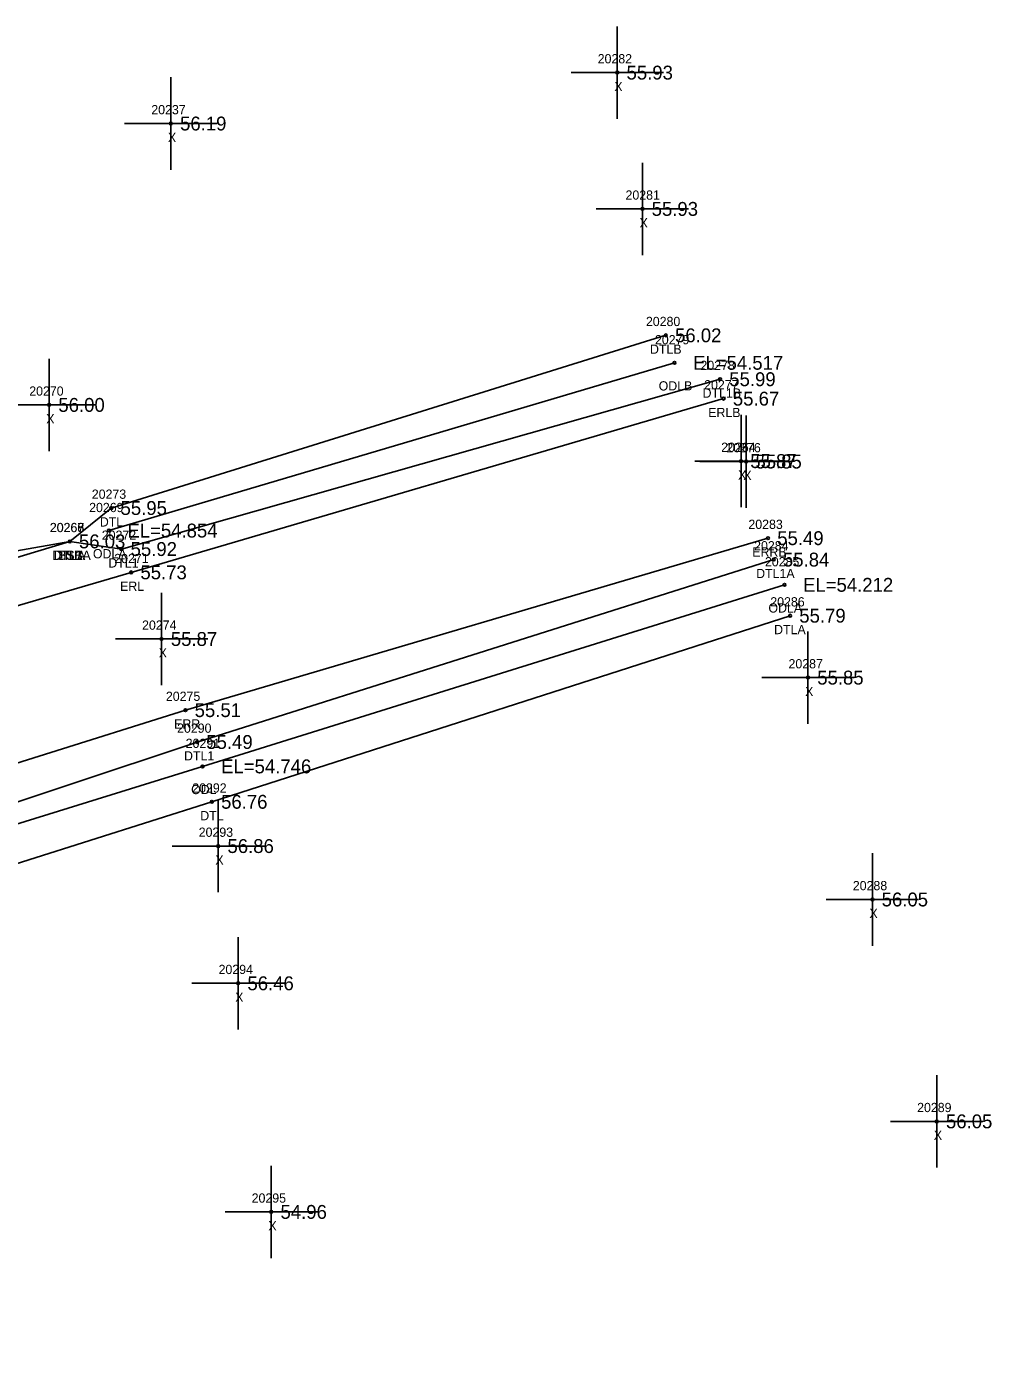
# Model space of a CAD drawing. Extents: x 2396547 to 2397655, y 770185 to 772649.
# Drawn here: x 2397051.2 to 2397155.6, y 771642.4 to 771785.4 of the extents above; entities that cross this region are included whole.
import ezdxf

# ---------------------------------------------------------------- set-up
doc = ezdxf.new("R2010")
doc.units = 0
for name, color, linetype in [('RD_DTM_BkLn2', 7, 'Continuous'), ('RD_DTM_BkLn_txCode', 7, 'Continuous'), ('RD_EX_H2O', 7, 'Continuous'), ('RD_EX_H2O_txCode', 7, 'Continuous'), ('RD_EX_Misc', 7, 'Continuous'), ('RD_EX_Misc_txCode', 7, 'Continuous'), ('RD_EX_Road', 7, 'Continuous'), ('RD_EX_Road_txCode', 7, 'Continuous'), ('RD_EX_TX_H2O_ELEV', 7, 'Continuous'), ('RD_EX_TX_Misc_ELEV', 7, 'Continuous'), ('RD_EX_TX_Road_ELEV', 7, 'Continuous'), ('RD_SMD_Locator', 7, 'Continuous')]:
    doc.layers.add(name, color=color, linetype=linetype)

msp = doc.modelspace()

# ---------------------------------------------------------------- linework, layer by layer
at = {"layer": 'RD_DTM_BkLn2'}
for points in [[(2397001.88, 771713.39), (2397031.24, 771722.25), (2397055.87, 771729.7)], [(2397001.88, 771713.39), (2397006.36, 771717.3), (2397030.46, 771725.22), (2397055.87, 771729.7)]]:
    msp.add_lwpolyline(points, dxfattribs=at)
at = {"layer": 'RD_EX_H2O'}
msp.add_line((2397060.11, 771730.87), (2397121.33, 771749.03), dxfattribs=at)
for points in [[(2397055.87, 771729.7), (2397060.37, 771733.31), (2397120.38, 771752)], [(2397055.87, 771729.7), (2397061.46, 771728.87), (2397126.25, 771747.25)], [(2397132.06, 771727.73), (2397069.65, 771707.99), (2397027.41, 771693.94), (2396997.29, 771683.71), (2397009.52, 771621.94), (2397039.8, 771510.33), (2397059.22, 771428.3), (2397068.26, 771415.82), (2397065.8, 771409.74)], [(2397133.23, 771725), (2397070.25, 771705.35), (2397027.65, 771692.13), (2397008.03, 771684.24), (2397003.46, 771682.97), (2397004.86, 771679.14), (2397019.55, 771624.25), (2397050.23, 771512.98), (2397072.95, 771431.23), (2397072.81, 771420.44), (2397072.44, 771413.81)], [(2397133.83, 771721.66), (2397071.25, 771701.52), (2397031.62, 771688.97), (2397008.91, 771681.79), (2397013.82, 771672.05), (2397025.11, 771625.88), (2397054.64, 771514.68), (2397075.97, 771429.94), (2397072.44, 771413.81)]]:
    msp.add_lwpolyline(points, dxfattribs=at)
at = {"layer": 'RD_EX_Misc'}
for p, q in [((2397115.13, 771775.43), (2397115.13, 771785.43)), ((2397066.81, 771769.92), (2397066.81, 771779.92)), ((2397110.13, 771780.43), (2397120.13, 771780.43)), ((2397061.81, 771774.92), (2397071.81, 771774.92)), ((2397117.85, 771760.68), (2397117.85, 771770.68)), ((2397112.85, 771765.68), (2397122.85, 771765.68)), ((2397053.64, 771739.47), (2397053.64, 771749.47)), ((2397048.64, 771744.47), (2397058.64, 771744.47)), ((2397128.52, 771733.39), (2397128.52, 771743.39)), ((2397129.08, 771733.34), (2397129.08, 771743.34)), ((2397123.52, 771738.39), (2397133.52, 771738.39)), ((2397124.08, 771738.34), (2397134.08, 771738.34)), ((2397065.81, 771714.14), (2397065.81, 771724.14)), ((2397060.81, 771719.14), (2397070.81, 771719.14)), ((2397135.77, 771709.96), (2397135.77, 771719.96)), ((2397130.77, 771714.96), (2397140.77, 771714.96)), ((2397071.94, 771691.73), (2397071.94, 771701.73)), ((2397066.94, 771696.73), (2397076.94, 771696.73)), ((2397142.74, 771685.95), (2397142.74, 771695.95)), ((2397137.74, 771690.95), (2397147.74, 771690.95)), ((2397074.1, 771676.88), (2397074.1, 771686.88)), ((2397069.1, 771681.88), (2397079.1, 771681.88)), ((2397149.7, 771661.94), (2397149.7, 771671.94)), ((2397144.7, 771666.94), (2397154.7, 771666.94)), ((2397077.68, 771652.14), (2397077.68, 771662.14)), ((2397072.68, 771657.14), (2397082.68, 771657.14))]:
    msp.add_line(p, q, dxfattribs=at)
at = {"layer": 'RD_EX_Road'}
for points in [[(2396998.08, 771710.28), (2397032.74, 771717.63), (2397062.52, 771726.35), (2397126.64, 771745.15)], [(2397002.95, 771693.12), (2397036.69, 771701.48), (2397068.39, 771711.44), (2397131.44, 771730.05)]]:
    msp.add_lwpolyline(points, dxfattribs=at)
at = {"layer": 'RD_SMD_Locator'}
for centre in [(2397115.13, 771780.43), (2397066.81, 771774.92), (2397117.85, 771765.68), (2397120.38, 771752), (2397121.33, 771749.03), (2397126.25, 771747.25), (2397126.64, 771745.15), (2397053.64, 771744.47), (2397128.52, 771738.39), (2397129.08, 771738.34), (2397060.37, 771733.31), (2397060.11, 771730.87), (2397055.87, 771729.7), (2397055.87, 771729.7), (2397055.87, 771729.7), (2397055.87, 771729.7), (2397131.44, 771730.05), (2397061.46, 771728.87), (2397132.06, 771727.73), (2397062.52, 771726.35), (2397133.23, 771725), (2397133.83, 771721.66), (2397065.81, 771719.14), (2397135.77, 771714.96), (2397068.39, 771711.44), (2397069.65, 771707.99), (2397070.25, 771705.35), (2397071.25, 771701.52), (2397071.94, 771696.73), (2397142.74, 771690.95), (2397074.1, 771681.88), (2397149.7, 771666.94), (2397077.68, 771657.14)]:
    msp.add_circle(centre, 0.15, dxfattribs=at)

# ---------------------------------------------------------------- texts
at = {"layer": 'RD_DTM_BkLn_txCode'}
for s, p in [('20266', (2397053.71, 771730.7)), ('20265', (2397053.73, 771730.7)), ('TSB', (2397054.61, 771727.7)), ('BSB', (2397054.62, 771727.7))]:
    msp.add_text(s, height=1, dxfattribs=at).set_placement(p)
at = {"layer": 'RD_EX_H2O_txCode'}
for s, p in [('20280', (2397118.23, 771753)), ('20279', (2397119.21, 771751.03)), ('DTLB', (2397118.67, 771750)), ('20278', (2397124.13, 771748.25)), ('ODLB', (2397119.61, 771746.03)), ('DTL1B', (2397124.36, 771745.25)), ('20273', (2397058.26, 771734.31)), ('20269', (2397057.97, 771732.87)), ('DTL', (2397059.13, 771731.31)), ('20267', (2397053.73, 771730.7)), ('20268', (2397053.73, 771730.7)), ('20272', (2397059.34, 771729.87)), ('20284', (2397129.94, 771728.73)), ('DTL1A', (2397053.98, 771727.7)), ('DTLA', (2397054.14, 771727.7)), ('ODLA', (2397058.38, 771727.87)), ('DTL1', (2397060.05, 771726.87)), ('20285', (2397131.11, 771727)), ('DTL1A', (2397130.16, 771725.73)), ('20286', (2397131.69, 771722.66)), ('ODLA', (2397131.49, 771722)), ('DTLA', (2397132.1, 771719.66)), ('20290', (2397067.49, 771708.99)), ('20291', (2397068.42, 771707.35)), ('DTL1', (2397068.24, 771705.99)), ('20292', (2397069.13, 771702.52)), ('ODL', (2397069.01, 771702.35)), ('DTL', (2397070, 771699.52))]:
    msp.add_text(s, height=1, dxfattribs=at).set_placement(p)
at = {"layer": 'RD_EX_Misc_txCode'}
for s, p in [('20282', (2397113.01, 771781.43)), ('X', (2397114.81, 771778.43)), ('20237', (2397064.7, 771775.92)), ('X', (2397066.5, 771772.92)), ('20281', (2397116.02, 771766.68)), ('X', (2397117.54, 771763.68)), ('20270', (2397051.49, 771745.47)), ('X', (2397053.33, 771742.47)), ('20264', (2397126.38, 771739.39)), ('20276', (2397126.94, 771739.34)), ('X', (2397128.21, 771736.39)), ('X', (2397128.77, 771736.34)), ('20274', (2397063.7, 771720.14)), ('X', (2397065.5, 771717.14)), ('20287', (2397133.66, 771715.96)), ('X', (2397135.46, 771712.96)), ('20293', (2397069.83, 771697.73)), ('X', (2397071.63, 771694.73)), ('20288', (2397140.62, 771691.95)), ('X', (2397142.42, 771688.95)), ('20294', (2397071.98, 771682.88)), ('X', (2397073.78, 771679.88)), ('20289', (2397147.58, 771667.94)), ('X', (2397149.39, 771664.94)), ('20295', (2397075.56, 771658.14)), ('X', (2397077.37, 771655.14))]:
    msp.add_text(s, height=1, dxfattribs=at).set_placement(p)
at = {"layer": 'RD_EX_Road_txCode'}
for s, p in [('20277', (2397124.53, 771746.15)), ('ERLB', (2397124.97, 771743.15)), ('20283', (2397129.32, 771731.05)), ('20271', (2397060.69, 771727.35)), ('ERRB', (2397129.74, 771728.05)), ('ERL', (2397061.32, 771724.35)), ('20275', (2397066.28, 771712.44)), ('ERR', (2397067.17, 771709.44))]:
    msp.add_text(s, height=1, dxfattribs=at).set_placement(p)
at = {"layer": 'RD_EX_TX_H2O_ELEV'}
for s, p in [('56.02', (2397121.38, 771751.25)), ('EL=54.517', (2397123.33, 771748.28)), ('55.99', (2397127.25, 771746.5)), ('55.95', (2397061.37, 771732.56)), ('EL=54.854', (2397062.11, 771730.12)), ('56.03', (2397056.87, 771728.95)), ('56.03', (2397056.87, 771728.95)), ('55.92', (2397062.46, 771728.12)), ('55.84', (2397133.06, 771726.98)), ('EL=54.212', (2397135.23, 771724.25)), ('55.79', (2397134.83, 771720.91)), ('55.49', (2397070.65, 771707.24)), ('EL=54.746', (2397072.25, 771704.6)), ('56.76', (2397072.25, 771700.77))]:
    msp.add_text(s, height=1.5, dxfattribs=at).set_placement(p)
at = {"layer": 'RD_EX_TX_Misc_ELEV'}
for s, p in [('55.93', (2397116.13, 771779.68)), ('56.19', (2397067.81, 771774.17)), ('55.93', (2397118.85, 771764.93)), ('56.00', (2397054.64, 771743.72)), ('55.87', (2397129.52, 771737.64)), ('55.85', (2397130.08, 771737.59)), ('56.03', (2397056.87, 771728.95)), ('56.03', (2397056.87, 771728.95)), ('55.87', (2397066.81, 771718.39)), ('55.85', (2397136.77, 771714.21)), ('56.86', (2397072.94, 771695.98)), ('56.05', (2397143.74, 771690.2)), ('56.46', (2397075.1, 771681.13)), ('56.05', (2397150.7, 771666.19)), ('54.96', (2397078.68, 771656.39))]:
    msp.add_text(s, height=1.5, dxfattribs=at).set_placement(p)
at = {"layer": 'RD_EX_TX_Road_ELEV'}
for s, p in [('55.67', (2397127.64, 771744.4)), ('55.49', (2397132.44, 771729.3)), ('55.73', (2397063.52, 771725.6)), ('55.51', (2397069.39, 771710.69))]:
    msp.add_text(s, height=1.5, dxfattribs=at).set_placement(p)

doc.saveas('drawing.dxf')
